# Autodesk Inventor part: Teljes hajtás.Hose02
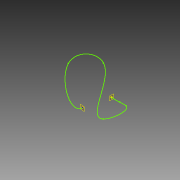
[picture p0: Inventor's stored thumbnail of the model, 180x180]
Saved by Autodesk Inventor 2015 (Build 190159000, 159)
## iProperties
ActiveState: True
Angle: UnInitValue
BendRadius: 0.500 in
CouplingKey: UnInitValue
DefaultBendRadius: UnInitValue
Diameter: 1/4
DiameterType: Nominal
Elbow45Key: UnInitValue
Elbow90Key: UnInitValue
ElbowCustomKey: UnInitValue
Ending: UnInitValue
FittingMaterial: UnInitValue
FittingStandard: UnInitValue
FlangeKey: UnInitValue
Gap: UnInitValue
GasketKey: UnInitValue
ID: 0,635
IsButtWelded: UnInitValue
IsFlanged: UnInitValue
IsSelfDraining: UnInitValue
Material: UnInitValue
MixedUnits: UnInitValue
Name: Hydraulic Hose - No Fittings
OD: 1,4986
PipeKey: v3#d489867e-ac9b-47ea-b952-0a1b885f66be#1
PipeType: Flexible Hose
PipingComponentColor: Blue - Wall Paint - Glossy
RoundUpValue: 0.125 in
RouteDirection45: UnInitValue
RouteDirection90: UnInitValue
Schedule: ID=0.25
ShowGap: UnInitValue
Standard: UnInitValue
SuppressEndFitting: True
SuppressStartFitting: True
UseFlangsForCouplings: UnInitValue
UseSubASM: True
_ComponentInfo: <CS><C N="Pipe" R="0,749300" OR="0,749300" IR="0,317500" PL="PL" PartType="pipe" SymKey="" PN="Parker hidraulikatömlő - No Skive 1/4"><CO N="1"><FE V="0"/><FD V
StyleName: _Piping Style 20
Created: 2013-02
Part Number: Teljes hajtás.Hose02
Material: Generic
Document SubType Name: Modeling
Designer: Marci
Density: 1 g/cm^3
Appearance: Default
_PSKETCH_SNAP: False
_PSKETCH_RSNP: False
_BASENETWORK_NOTAUTODIMENSION: False
Author: Marci
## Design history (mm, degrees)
workpoint "Work Point1"
workplane "Work Plane1"
workpoint "Work Point2"
workplane "Work Plane2"
sketch "3D Sketch1" dims "d0" = 10, "d1" = 0.1 (derived), "d2" = 10, "d3" = 0.1 (derived)
other parameters: "B" = 12.7 [user parameter]
